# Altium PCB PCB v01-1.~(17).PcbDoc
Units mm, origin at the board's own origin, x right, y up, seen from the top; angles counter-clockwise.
Board outline 287 x 161 mm, 2 copper layers (Top Layer, Bottom Layer); 82 components, 36 nets, 164 pads, 8 vias.
Unrouted connection lines stored in the file: 30.
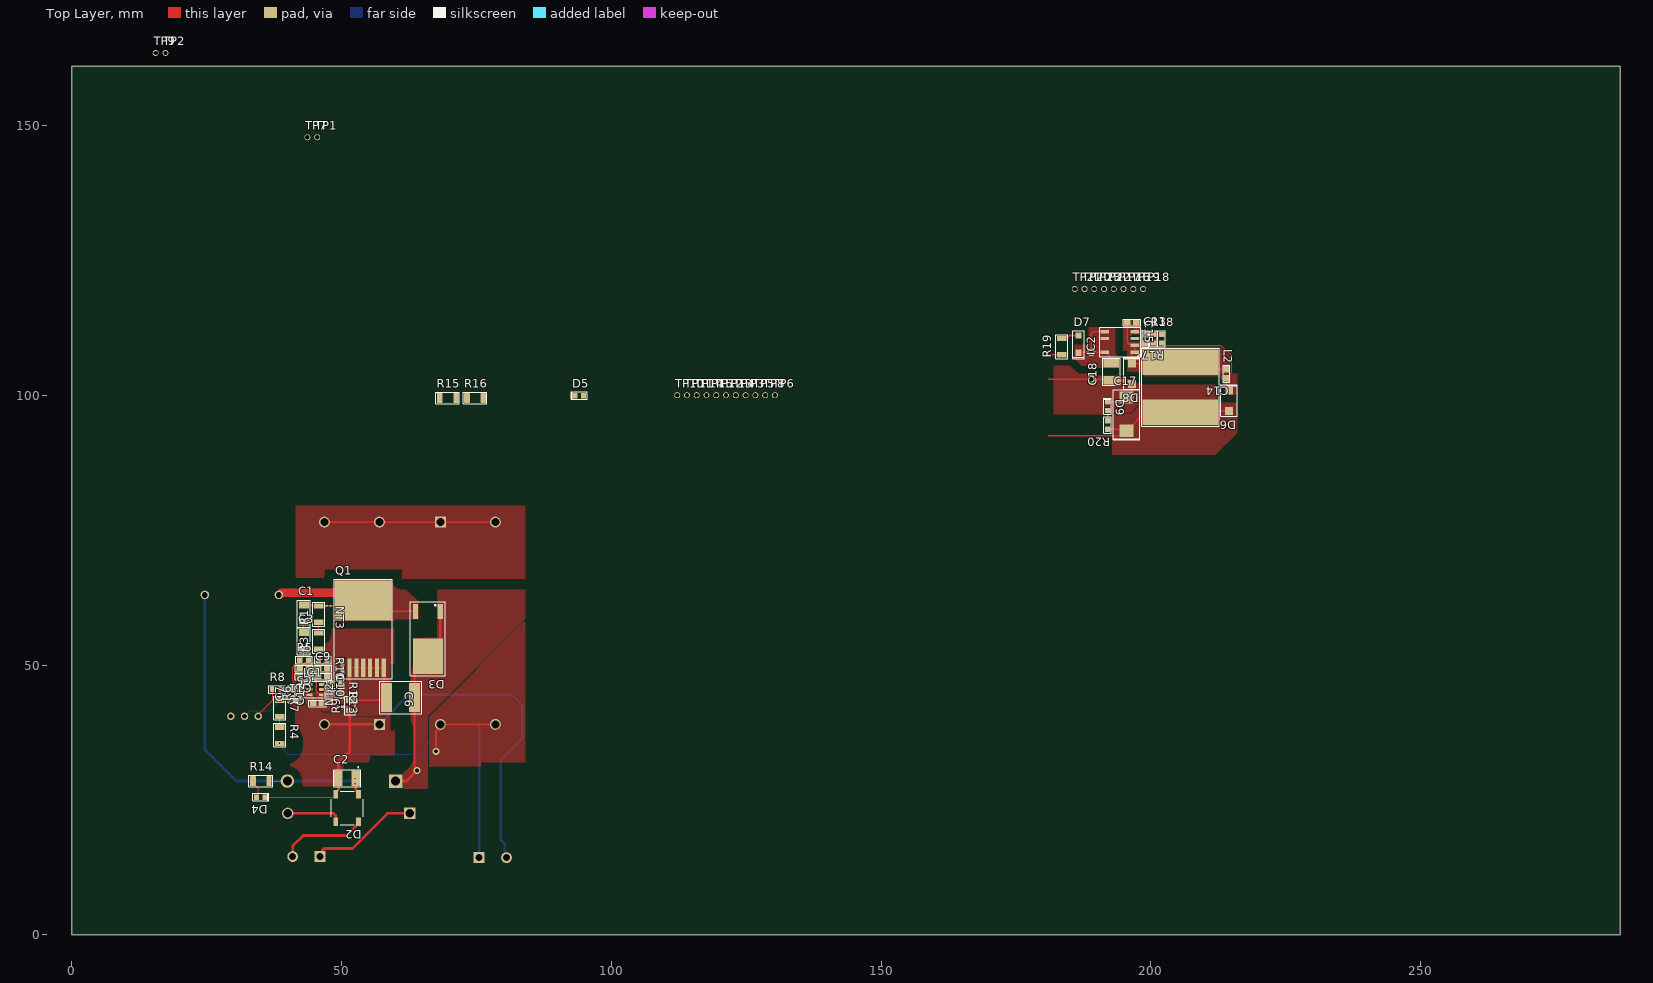
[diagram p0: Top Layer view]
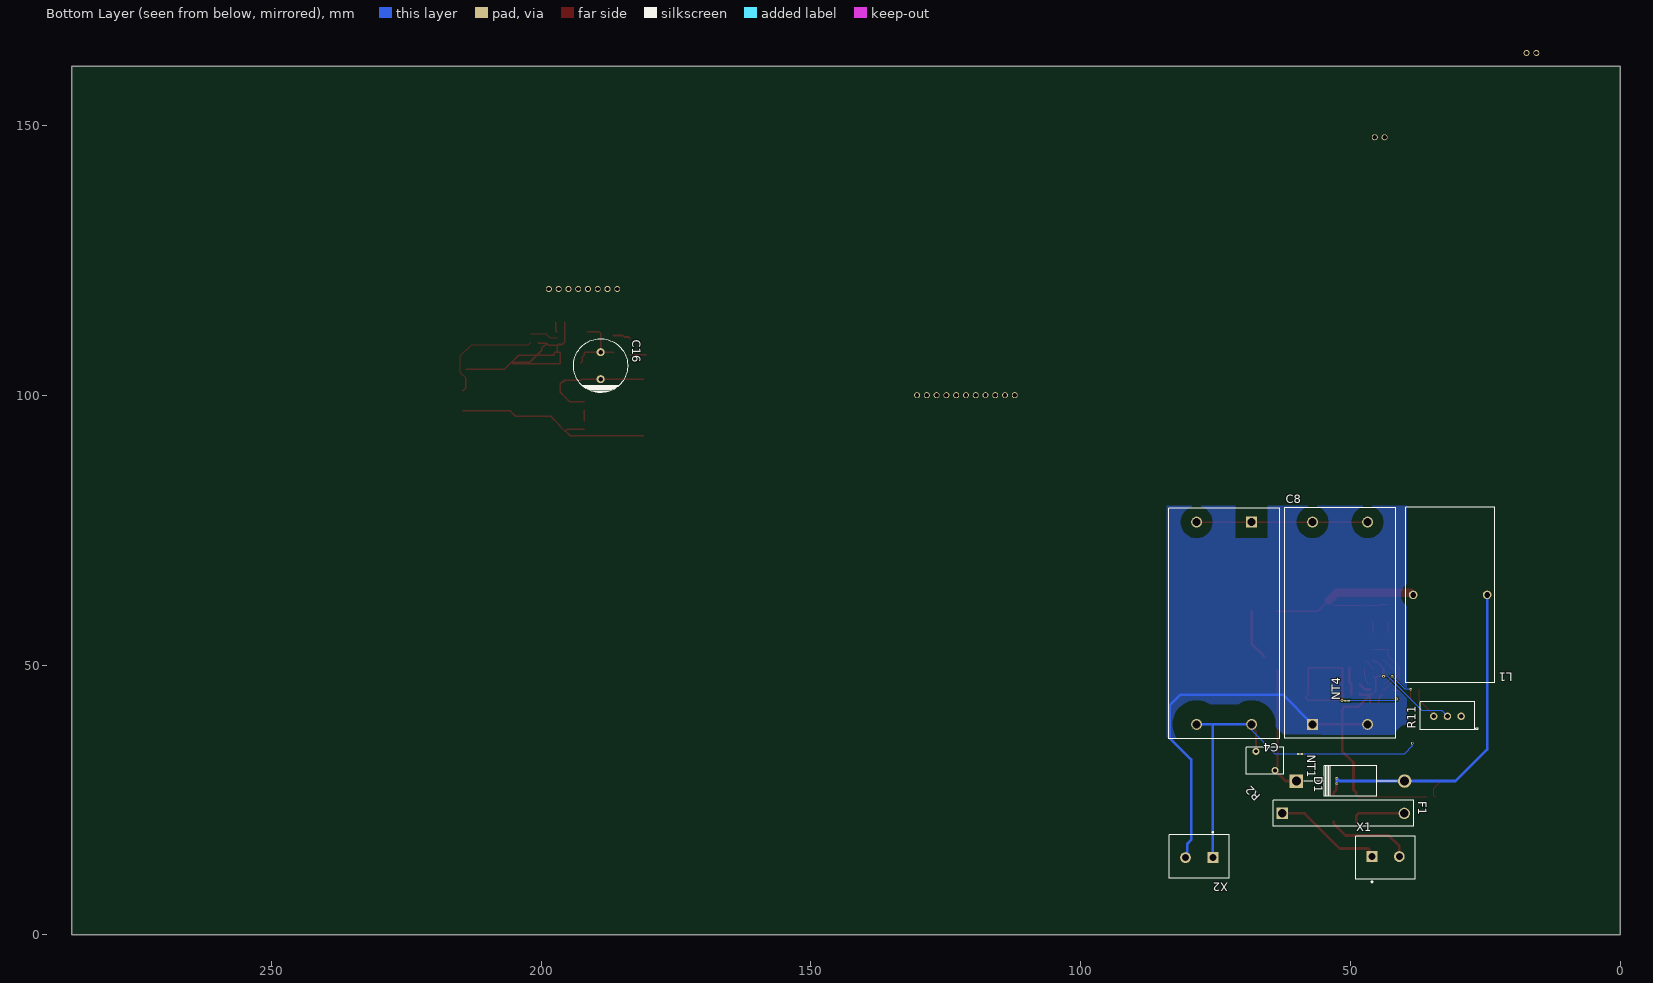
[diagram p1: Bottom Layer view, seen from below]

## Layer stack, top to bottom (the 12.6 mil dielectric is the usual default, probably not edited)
Top Solder: solder mask 0.0102, Solder Resist, Dk 3.5
Top Layer: signal copper 0.0356
Dielectric 1: dielectric 0.32, FR-4, Dk 4.8
Bottom Layer: signal copper 0.0356
Bottom Solder: solder mask 0.0102, Solder Resist, Dk 3.5

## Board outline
0,0 287,0 287,161 0,161

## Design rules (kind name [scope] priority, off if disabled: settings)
BoardOutlineClearance [All] p1: gap=1 ignorepadtopadclearanceinfootprint=FALSE
Clearance "1000V vs other" [InNetClass('1000V') vs Not InNetClass('1000V') AND Not InNetClass('500V')] p1: gap=3.5 ignorepadtopadclearanceinfootprint=TRUE
Clearance "500V vs other" [InNetClass('500V') vs Not InNetClass('500V')] p2: gap=2 ignorepadtopadclearanceinfootprint=TRUE
Clearance "375Vac vs other" [InNetClass('375Vac') vs Not InNetClass('375Vac')] p3: gap=1.5 ignorepadtopadclearanceinfootprint=FALSE
Clearance "375V vs other" [InNetClass('375V') vs Not InNetClass('375V')] p4: gap=1.5 ignorepadtopadclearanceinfootprint=FALSE
Clearance "AC vs ALL" [InNetClass('AC')] p5: gap=1.5 ignorepadtopadclearanceinfootprint=FALSE
Clearance Minimal [All] p6: gap=0.2 ignorepadtopadclearanceinfootprint=FALSE
Height [All] p1: minheight=0 maxheight=100 prefheight=12.7
HoleSize [All] p1: absolutevalues=TRUE maxlimit=10 minlimit=0.2 maxpercent=80.000 minpercent=20.000
PolygonConnect [All] p1: thpad.connectstyle=Relief thpad.reliefconductorwidth=0.254 thpad.reliefentries=4 thpad.polygonreliefangle="90 Angle" thpad.airgapwidth=0.2 smdpad.connectstyle=Relief smdpad.reliefconductorwidth=0.254 smdpad.reliefentries=4 smdpad.polygonreliefangle="90 Angle" smdpad.airgapwidth=0.2 via.connectstyle=Direct via.reliefconductorwidth=0.254 via.reliefentries=4 via.polygonreliefangle="90 Angle" via.airgapwidth=0.254
RoutingVias [All] p1: holewidth=0.2 width=0.5 viastyle="Through Hole" minholewidth=0.2 minwidth=0.5 maxholewidth=10 maxwidth=10
SolderMaskExpansion [All] p1: expansion=0.102 istentingtop=FALSE
Width [All] p1: maxlimit=20 minlimit=0.2 preferedwidth=0.3
28 further rules are at their usual default settings.

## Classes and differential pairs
net class 500V: NetC4_1 NetR4_1 NetR15_1
net class 1000V: NetC6_2 NetNT1_2 Udc
net class AC: L L_fuse N
net class 375V: HVIN NetD7_A ""
net class 375Vac: DRAIN FB NetC1_1 NetC1_2 NetC14_2 NetR1_1 SW VDD

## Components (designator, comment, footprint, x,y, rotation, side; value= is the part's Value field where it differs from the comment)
C1 "Generic Capacitor model" CAP_1206 43,59.55 r90 top
C2 "Generic Capacitor model" CAP_1210 51,29 r0 top
C3 "Generic Capacitor model" CAP_1206 43,54.4 r90 top
C4 "Generic Capacitor model" C4AQCBW5200A3FJ 68.3,76.5 r270 bottom
C5 "Generic Capacitor model" "CAP 0603" 43.025,49.4 r180 top
C6 "Generic Capacitor model" CAP_2220 58.34,44 r0 top
C7 "Generic Capacitor model" "CAP 0603" 40.7,44.65 r90 top
C8 "Generic Capacitor model" C4AQCBW5200A3FJ 57,39 r90 bottom
C9 "Generic Capacitor model" "CAP 0603" 46.525,49.4 r0 top
C10 "Generic Capacitor model" "CAP 0603" 46.525,47.9 r0 top
C11 "Generic Capacitor model" "CAP 0603" 43.025,47.9 r180 top
C12 "Generic Capacitor model" "CAP 0603" 45.525,42.9 r180 top
C13 "Generic Capacitor model" "CAP 0603" 199,110.5 r90 top
C14 "Generic Capacitor model" "CAP 0603" 214,104 r270 top
C15 "Generic Capacitor model" "CAP 0603" 196.5,113.5 r0 top
C16 "Cap_Polarized" "ELKO 10X20MM" 189,105.5 r270 bottom
C17 "Cap_Tantal" CAP_TANTAL_2917 195.5,96.5 r90 top
C18 "Generic Capacitor model" CAP_1210 192.7,104.4 r90 top
D1 "Diode" DO-201AD 60,28.5 r180 bottom
D2 "CD-MBL206SL" CD-MBL206SL 51,23.5 r270 top
D3 "Diode Schottky" TO252-2_DPAK_B 66,53.5 r180 top
D4 "Diode LED Red" DIODE_0603 35,25.5 r180 top
D5 "Diode LED Red" DIODE_0603 94.068,99.931 r0 top
D6 "Diode Schottky" SMAF 214.5,99 r270 top
D7 "Diode" SOD-123FL 186.6,109.5 r90 top
D8 "Diode Schottky" SMAF 196.5,104 r270 top
D9 "Diode LED Blue" DIODE_0603 192,98 r270 top
F1 "64600001003" 64600001003 62.6,22.5 r180 bottom
IC1 "UCC28056A" SOT-23-6 44.025,46.4 r0 top
IC2 "UCC28881" SOIC-7 197,108 r180 top
L1 "HCTI-680-3.4" HCTI-680-3.4 31.5,63 r0 bottom
L2 "SDR1307-681KL" SDR1307-681KL 205.5,101.5 r270 top
NT1 "NT" NETTIE_0.3MM 59.325,33.5 r180 bottom net-tie
NT2 "NT" NETTIE_0.5MM 49.75,42.25 r180 top net-tie
NT3 "NT" NETTIE_0.3MM 47.6,61 r0 top net-tie
NT4 "NT" NETTIE_0.3MM 50.6,43.4 r0 bottom net-tie
Q1 "Nmos_KS" "TO-263-7 D2PAK" 54,59.1 r0 top
R1 "Generic resistor model" RES_1206 45.75,59.4 r90 top
R2 "NTC 10R 1A" ICL101D05MIB 63.964,30.464 r45 bottom
R3 "Generic resistor model" RES_1206 45.75,54.4 r90 top
R4 "Generic resistor model" RES_1206 38.5,37.035 r270 top
R5 "Generic resistor model" RES_0603 43.025,50.9 r0 top
R6 "Generic resistor model" RES_0603 42.2,44.65 r90 top
R7 "Generic resistor model" RES_1206 38.5,42.04 r270 top
R8 "Generic resistor model" RES_0603 38,45.5 r0 top
R9 "Generic resistor model" Res_0805 51.5,42.5 r90 top
R10 "Generic resistor model" RES_0603 46.525,50.9 r0 top
R11 "67WR25KLF" RES-67WR10KLF 29.46,40.5 r0 bottom
R12 "Generic resistor model" RES_0603 49.025,46.4 r0 top
R13 "Generic resistor model" RES_0603 49.025,44.65 r0 top
R14 "Generic resistor model" RES_1206 35,28.5 r0 top
R15 "Generic resistor model" RES_1206 69.645,99.506 r0 top
R16 "Generic resistor model" RES_1206 74.703,99.506 r0 top
R17 "Generic resistor model" RES_0603 202,110.5 r270 top
R18 "Generic resistor model" RES_0603 200.5,110.5 r90 top
R19 "Generic resistor model" RES_1206 183.5,109 r90 top
R20 "Generic resistor model" RES_0603 192,94.5 r270 top
TP1 "Test Point" TEST_POINT_THT 45.456,147.84 r90 top
TP2 "Test Point" TEST_POINT_THT 17.325,163.482 r90 top
TP3 "Test Point" TEST_POINT_THT 124.888,100.029 r90 top
TP4 "Test Point" TEST_POINT_THT 123.077,100.029 r90 top
TP5 "Test Point" TEST_POINT_THT 126.699,100.029 r90 top
TP6 "Test Point" TEST_POINT_THT 130.322,100.029 r90 top
TP7 "Test Point" TEST_POINT_THT 43.644,147.84 r90 top
TP8 "Test Point" TEST_POINT_THT 128.51,100.029 r90 top
TP9 "Test Point" TEST_POINT_THT 15.514,163.482 r90 top
TP10 "Test Point" TEST_POINT_THT 112.21,100.029 r90 top
TP11 "Test Point" TEST_POINT_THT 114.021,100.029 r90 top
TP12 "Test Point" TEST_POINT_THT 119.454,100.029 r90 top
TP13 "Test Point" TEST_POINT_THT 121.266,100.029 r90 top
TP14 "Test Point" TEST_POINT_THT 115.832,100.029 r90 top
TP15 "Test Point" TEST_POINT_THT 117.643,100.029 r90 top
TP16 "Test Point" TEST_POINT_THT 194.962,119.716 r90 top
TP17 "Test Point" TEST_POINT_THT 193.15,119.716 r90 top
TP18 "Test Point" TEST_POINT_THT 198.584,119.716 r90 top
TP19 "Test Point" TEST_POINT_THT 196.773,119.716 r90 top
TP20 "Test Point" TEST_POINT_THT 187.717,119.716 r90 top
TP21 "Test Point" TEST_POINT_THT 185.906,119.716 r90 top
TP22 "Test Point" TEST_POINT_THT 191.339,119.716 r90 top
TP23 "Test Point" TEST_POINT_THT 189.528,119.716 r90 top
X1 "Screw Terminal 2pos" "Screw terminal 2pos 5.08mm" 43.485,14.3 r180 bottom
X2 "Screw Terminal 2pos" "Screw terminal 2pos 5.08mm" 78,14.5 r0 bottom

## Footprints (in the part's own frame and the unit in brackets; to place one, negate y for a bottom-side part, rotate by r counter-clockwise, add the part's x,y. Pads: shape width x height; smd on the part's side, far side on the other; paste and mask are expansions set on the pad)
64600001003 [mil] "Fuse holder 5x20mm"
  rect 83x83 / inner round 60 / far side rect 83x83 hole 63 paste-41.5 mask+0: 1(0,0)
  round 83 / inner round 60 / far side round 83 hole 63 paste-41.5 mask+0: 2(889.76,0)
  silkscreen extent -67,-94 961,94, body extent -62,-89 954,89, height 392
C4AQCBW5200A3FJ [mil] "Film Capacitor"
  round 79 hole 59 paste-39.5 mask+0: 1(0,-401.57) 2(1476.38,0) 2(1476.38,-401.58)
  rect 79x79 hole 59 paste-39.5 mask+0: 1(0,0)
  silkscreen extent -102,-606 1583,205, body extent -98,-602 1579,201, height 1583
"CAP 0603" [mm] "CAP 0603"
  rect 1.2x1 smd paste+0 mask+0: 1(-0.825,0) 2(0.825,0)
  silkscreen extent -1.6,-0.6 1.6,0.6, body extent -0.87,-0.48 0.87,0.48, height 0.87
CAP_1206 [mm]
  rect 1.3x1.8 smd: 1(-1.6,0) 2(1.6,0)
  silkscreen extent -2.5,-1.2 2.5,1.2, body extent -1.7,-0.9 1.7,0.9, height 1.81
CAP_1210 [mm] "Cap SMD 1210"
  rect 1.6x2.904 smd paste+0 mask+0: 1(-1.6,0) 2(1.6,0)
  silkscreen extent -2.5,-1.6 2.5,1.6, body extent -2.85,-1.95 2.85,1.95, height 0.25
CAP_2220 [mm] "CAP_2220"
  rect 2.01x5.4 smd: 1(0,0) 2(5.16,0)
  silkscreen extent -1.3,-3 6.5,3
CAP_TANTAL_2917 [mm] "CAP TANTAL 2917"
  rect 2.31x2.52 smd: +(-3.1,0) -(3.1,0)
  silkscreen extent -4.75,-2.5 4.5,2.5, body extent -3.65,-2.15 3.65,2.15, height 3.11
CD-MBL206SL [mil] "Rectifier bridge"
  rect 62.75x35.03 smd paste+0 mask+0: +(-100.37,82.5) -(-100.37,-82.5) AC1(100.37,82.5) AC2(100.37,-82.5)
  silkscreen extent -303,-114 122,114, body extent -116,-106 116,106, height 46
DIODE_0603 [mm] "RES 0603"
  rrect20% 0.94x1.02 smd: A(0.79,0) K(-0.79,0)
  silkscreen extent -1.5,-0.7 1.5,0.7, body extent -0.8,-0.4 0.8,0.4, height 0.46
DO-201AD [mm] "Diode THT Vishay"
  round 2.5 hole 1.651 paste-1.079 mask+0: A(20.066,0)
  rect 2.5x2.5 hole 1.651 paste-1.079 mask+0: K(0,0)
  silkscreen extent 1.4,-2.8 18.7,2.8, body extent -0.7,-2.67 20.76,2.67, height 5.34
"ELKO 10X20MM" [mm] "ELKO THT 10x20mm 5mm Pitch"
  round 1.5 hole 0.85: +(-2.5,0) -(2.5,0)
  silkscreen extent -5,-5 5,5, body extent -5,-5 5,5, height 20
HCTI-680-3.4 [mm] "Toroidal Inductor"
  round 1.6 hole 1.06: 1(-6.858,0) 2(6.858,0)
  silkscreen extent -8.25,-16.26 8.25,16.26, body extent -8.25,-16.21 8.26,16.21, height 34.27
ICL101D05MIB [mm] "NTC THT 5mm Disk"
  round 1.3 hole 0.7: 1(0,0) 2(5,0)
  silkscreen extent -1.67,-4.17 6.82,4.32
NETTIE_0.3MM [mm] "NetTie 0.3mm"
  rect 0.45x0.3 smd paste-5 mask+0.102: 1(-0.325,0) 2(0.325,0)
  Top Layer region: -0.125,0.15 0.125,0.15 0.125,-0.15 -0.125,-0.15
NETTIE_0.5MM [mm] "NetTie 0.5mm"
  rect 0.5x0.5 smd paste-5 mask+0.102: 1(-0.4,0) 2(0.4,0)
  Top Layer region: -0.175,-0.25 0.175,-0.25 0.175,0.25 -0.175,0.25
RES-67WR10KLF [mil] "Trimm Pot 10k"
  round 54 / inner round 60 / far side round 54 hole 34 paste-27 mask+0: 1(0,0) 2(100,0) 3(200,0)
  silkscreen extent -122,-105 300,100
RES_0603 [mm] "RES 0603"
  rrect20% 0.94x1.02 smd: 1(-0.79,0) 2(0.79,0)
  silkscreen extent -1.5,-0.7 1.5,0.7, body extent -0.8,-0.4 0.8,0.4, height 0.46
Res_0805 [mm]
  rrect25% 1x1.42 smd: 1(-0.925,-0.057) 2(0.945,-0.057)
  silkscreen extent -1.7,-1 1.7,0.9, body extent -1,-0.62 1,0.62, height 0.61
RES_1206 [mm]
  rrect14% 1.09x1.77 smd: 1(-1.465,0)
  rrect14% 0.94x1.77 smd: 2(1.54,0)
  silkscreen extent -2.2,-1.1 2.2,1.1, body extent -1.55,-0.78 1.55,0.77, height 0.56
"Screw terminal 2pos 5.08mm" [mm] "Screw terminal 2pos 5.08mm"
  rect 2x2 hole 1.3 paste-1000 mask+0: 1(-2.515,0.2)
  round 2 hole 1.3 paste-1000 mask+0: 2(2.565,0.2)
  silkscreen extent -5.56,-4.62 5.56,4, body extent -5.05,-3.93 5.11,4.07, height 10.02
SDR1307-681KL [mil] "Power inductor"
  rect 187x551 smd paste+0 mask+0: 1(-182,0) 2(182,0)
  silkscreen extent -283,-283 283,283
SMAF [mm] "DIODE SMAF"
  rect 1.46x1.53 smd: A(1.875,0) K(-1.875,0)
  silkscreen extent -3,-1.5 2.9,1.5, body extent -2.3,-1.3 2.3,1.3, height 1.11
SOD-123FL [mm]
  rect 1.18x1.17 smd: A(1.59,0) K(-1.59,0)
  silkscreen extent -2.7,-1.1 2.5,1.1, body extent -1.85,-0.95 1.85,0.95, height 1.35
SOIC-7 [mm] "SOIC-7"
  rect 1.55x0.6 smd: 1(0,0) 2(0,-1.27) 3(0,-2.54) 4(0,-3.81) 5(5.5,-3.81) 6(5.5,-2.54) 8(5.5,0)
  silkscreen extent -1.1,-4.6 6.5,0.8, body extent -0.2,-4.4 5.8,0.6, height 1.75
SOT-23-6 [mm]
  rect 1.072x0.532 smd: 1(0,0) 2(0,-0.95) 3(0,-1.9) 4(2.298,-1.9) 5(2.298,-0.95) 6(2.298,0)
  silkscreen extent -1.3,-2.5 3.2,0.6, body extent -0.3,-2.35 2.5,0.55, height 1.2
TEST_POINT_THT [mm] "Test point hole"
  round 1.1 hole 0.8: 1(0,0)
TO252-2_DPAK_B [mil] "Check internal diode connection pins!"
  rect 36.97x109.37 smd paste+0 mask+0: A(89.57,-253.97) K(-89.57,-253.97)
  rect 218x260 smd paste+0 mask+0: K(0,73)
  silkscreen extent -128,-325 128,217, body extent -132,-287 132,172, height 94
"TO-263-7 D2PAK" [mil] "SMD Mosfet"
  rect 409x294 smd paste+0 mask+0: D(0,113.5)
  rect 29.97x137.37 smd paste+0 mask+0: G(-150,-377.47) KS(-100,-377.47) S(-50,-377.47) S(0,-377.47) S(50,-377.47) S(100,-377.47) S(150,-377.47)
  silkscreen extent -213,-457 213,268, body extent -202,-424 202,241, height 180

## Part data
C1 C3: library part Cap, Capacitance=22p, Case Code (Imperial)=1206, Manufacturer=Walsin, Manufacturer Part Number=1206N220J102CT, Supplier Part Number 1=791-1206N220J102CT, Voltage Rating=1kV
C2 C18: library part Cap, Capacitance=100n, Case Code (Imperial)=1210, Manufacturer=Kemet, Manufacturer Part Number=C1210C104KBRACAUTO, Supplier Part Number 1=80-C1210C104KBRAUTO, Voltage Rating=630V
C4 C8: library part Cap, Capacitance=20u, Manufacturer=Kemet, Manufacturer Part Number=C4AQCBW5200A3FJ, Supplier Part Number 1=80-C4AQCBW5200A3FJ, Voltage Rating=650V
C5: library part Cap, Capacitance=10p, Case Code (Imperial)=0603, Manufacturer=Kemet, Manufacturer Part Number=C0603C100J1GAC, Supplier Part Number 1=80-C0603C100J1GAC, Voltage Rating=100V
C6: library part Cap, Capacitance=22n, Case Code (Imperial)=2220, Voltage Rating=2000V
C7: library part Cap, Capacitance=3n9, Case Code (Imperial)=0603, Manufacturer=Vishay, Manufacturer Part Number=VJ0603Y392KXACW1BC, Supplier Part Number 1=77-VJ0603Y392KXACBC, Voltage Rating=50V
C9 C14: library part Cap, Capacitance=180n, Case Code (Imperial)=0603, Manufacturer=Murata, Manufacturer Part Number=GCJ188R91H184KA01D, Supplier Part Number 1=81-GCJ188R91H184KA1D, Voltage Rating=50V
C10: library part Cap, Capacitance=82n, Case Code (Imperial)=0603, Manufacturer=Murata, Manufacturer Part Number=GCM188L81H823KA57D, Supplier Part Number 1=81-GCM188L81H823KA7D, Voltage Rating=50V
C11 C13: library part Cap, Capacitance=3n, Case Code (Imperial)=0603, Manufacturer=Murata, Manufacturer Part Number=GRM1885C1H302JA01D, Supplier Part Number 1=81-GRM1885C1H302JA1D, Voltage Rating=50V
C12 C15: library part Cap, Capacitance=3u3, Case Code (Imperial)=0603, Manufacturer=TDK, Manufacturer Part Number=C1608X5R1V335M080AC, Supplier Part Number 1=810-C1608X5R1V335M0C, Voltage Rating=35V
C16: "Generic polarized cap symbol", Capacitance=10u, Manufacturer=Panasonic, Manufacturer Part Number=EEU-EE2W100U, Supplier Part Number 1=667-EEU-EE2W100U, Voltage Rating=450V
C17: "Generic tantal cap symbol", Capacitance=100u, Manufacturer=Kemet, Manufacturer Part Number=T491X107M025AT, Supplier Part Number 1=80-T491X107M025, Voltage Rating=25V
D1: "General Diode symbol", Forward Current=3A, Manufacturer=Vishay, Manufacturer Part Number=BY255P-E3/73, Reverse Voltage=1300V, Supplier Part Number 1=625-BY255P-E3/73
D2: "Diode Bridge 600V 2A", Manufacturer=Bourns
D3: "General Schottky Diode symbol", Forward Current=2A, Manufacturer=Infineon, Manufacturer Part Number=IDM02G120C5XTMA1, Reverse Voltage=1200V, Supplier Part Number 1=726-IDM02G120C5XTMA1
D4 D5: "Generic red LED symbol"
D6 D8: "General Schottky Diode symbol", Forward Current=2A, Manufacturer=Comchip, Manufacturer Part Number=AES2JF-HF, Reverse Voltage=600V, Supplier Part Number 1=750-AES2JF-HF
D7: "General Diode symbol", Forward Current=1A, Manufacturer=MCC, Manufacturer Part Number=GS1Z-LTP, Reverse Voltage=2kV, Supplier Part Number 1=833-GS1Z-LTP
D9: "Generic blue LED symbol"
F1: "Fuse Holder 5X20MM 250V 6.3A", Manufacturer=Littlefuse, Supplier Part Number 1=576-64600001003
IC1: "PFC TM IC", Manufacturer="Texas Instruments"
IC2: "700-V Lowest Quiescent current off-line switcher", Manufacturer="Texas Instruments", Supplier Part Number 1=UCC28881D
L1: "Inductor THT 680uH 3.4A 150mR", Inductance=680u, Manufacturer="Bel Signal Transformer", Resistance=150mR, Saturation current=3.4Asat, Supplier Part Number 1=530-HCTI-680-3.4
L2: "Power Inductors - SMD 680uH 10% SMD 1307", Inductance=680u, Manufacturer=Bourns, Resistance=1R, Saturation current=1.2A, Supplier Part Number 1=652-SDR1307-681KL
NT1 NT2 NT3 NT4: library part NetTie, "Net Tie"
Q1: "Generic Nmos symbol with Kelvin Source", Manufacturer=GeneSiC, Manufacturer Part Number=G3R350MT12J, Supplier Part Number 1=905-G3R350MT12J, Voltage=1200V
R1 R3: library part Res, Case Code (Imperial)=1206, Manufacturer=ROHM, Manufacturer Part Number=KTR18EZPF4994, Resistance=4M99, Resistance Tolerance=1%, Supplier Part Number 1=755-KTR18EZPF4994
R2: library part ICL101D05MIB, "NTC 10R 1A 5mm THT", Manufacturer=Eaton, Resistance=10R, Supplier Part Number 1=504-ICL101D05MIB
R4 R7: library part Res, Case Code (Imperial)=1206, Manufacturer=ROHM, Manufacturer Part Number=KTR18EZPF5104, Resistance=5M1, Resistance Tolerance=1%, Supplier Part Number 1=755-KTR18EZPF5104
R5: library part Res, Case Code (Imperial)=0603, Manufacturer=Yageo, Manufacturer Part Number=AC0603JR-073KL, Resistance=3k, Supplier Part Number 1=603-AC0603JR-073KL
R6: library part Res, Case Code (Imperial)=0603, Manufacturer=Vishay, Manufacturer Part Number=CRCW060324K3FKEB, Resistance=24k3, Resistance Tolerance=1%, Supplier Part Number 1=71-CRCW060324K3FKEB
R8: library part Res, Case Code (Imperial)=0603, Manufacturer=Yageo, Manufacturer Part Number=RT0603DRE0725K5L, Resistance=25k5, Resistance Tolerance=1%, Supplier Part Number 1=603-RT0603DRE0725K5L
R9: library part Res, Case Code (Imperial)=0805, Manufacturer=Eaton, Manufacturer Part Number=MFLA0805R2000FA, Power Rating=250mW, Resistance=200mR, Supplier Part Number 1=504-MFLA0805R2000FA
R10: library part Res, Case Code (Imperial)=0603, Manufacturer=Panasonic, Manufacturer Part Number=ERJ-3EKF1653V, Resistance=165k, Resistance Tolerance=1%, Supplier Part Number 1=667-ERJ-3EKF1653V
R11: "Trimpot, 25 kohm, Through Hole, 20 Turns, Multi Turn, Cermet, Top Adjust,", Manufacturer="BI Technologies", Resistance=25k, Supplier Part Number 1=858-67WR25KLF
R12: library part Res, Case Code (Imperial)=0603, Power Rating=?mW, Resistance=10R, Resistance Tolerance=?%, Supplier Part Number 1=?
R13: library part Res, Case Code (Imperial)=0603, Power Rating=?mW, Resistance=82k, Resistance Tolerance=?%, Supplier Part Number 1=?
R14: library part Res, Case Code (Imperial)=1206, Manufacturer=KOA, Manufacturer Part Number=RN73H2BTTD3523F100, Power Rating=?mW, Resistance=352k, Resistance Tolerance=?%, Supplier Part Number 1=660-RN73H2BT3523F100
R15 R16: library part Res, Case Code (Imperial)=1206, Manufacturer=Yageo, Manufacturer Part Number=RT1206FRE07510KL, Power Rating=?mW, Resistance=510k, Resistance Tolerance=?%, Supplier Part Number 1=603-RT1206FRE07510KL
R17: library part Res, Case Code (Imperial)=0603, Manufacturer=Yageo, Manufacturer Part Number=RT0603BRD07135KL, Power Rating=?mW, Resistance=135k, Resistance Tolerance=1%, Supplier Part Number 1=603-RT0603BRD07135KL
R18: library part Res, Case Code (Imperial)=0603, Manufacturer=TE, Manufacturer Part Number=CRG0603F10K/10, Power Rating=?mW, Resistance=10k, Resistance Tolerance=1%, Supplier Part Number 1=279-CRG0603F10K/10
R19: library part Res, Case Code (Imperial)=1206, Manufacturer=Koa, Manufacturer Part Number=SG73P2BTTD100J, Power Rating=750mW, Resistance=10R, Supplier Part Number 1=660-SG73P2BTTD100J
R20: library part Res, Case Code (Imperial)=0603, Manufacturer=Kamaya, Manufacturer Part Number=RMC1/16K1502FTP, Resistance=15k, Supplier Part Number 1=791-RMC1/16K1502FTP
TP1 TP2 TP3 TP4 TP5 TP6 TP7 TP8 TP9 TP10 TP11 TP12 TP13 TP14 TP15 TP16 TP17 TP18 TP19 TP20 TP21 TP22 TP23: "Test point"
X1 X2: "Screw terminal 2 pos, pith 5.08mm", Color=Black, Current=15A, Current Rating=16A, Flammability Rating="UL94 V-0", Manufacturer=Weidmuller, Manufacturer Part Number=1760510000, Max Operating Temperature=120°C, Max Supply Voltage=300V, Min Operating Temperature=-50°C, Package Quantity=500, Supplier Part Number 1=4477091

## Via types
v1: diameter 0.5, hole 0.2, Top Layer to Bottom Layer, tented both sides, 8 vias

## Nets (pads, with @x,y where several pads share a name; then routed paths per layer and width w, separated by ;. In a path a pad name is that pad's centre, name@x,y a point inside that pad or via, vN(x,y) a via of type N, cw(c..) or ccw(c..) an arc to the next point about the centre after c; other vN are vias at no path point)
15V: C12.2 C17.+ D6.A IC1.3 L2.2 R20.2 TP19.1 | length 41.1
  Top Layer w0.3: IC1.3 44.295,44.5 44.411,44.384 44.411,44.114 44.7,43.825 C12.2 ; 181,92.5 194.6,92.5 C17.+ ; R20.2 195.19,93.71 C17.+ ; D6.A 205.748,97.125 L2.2 204.751,96.128 198.228,96.128 196.61,94.51 196.61,94.405 195.605,93.4 C17.+
COMP: C9.2 C10.2 IC1.6 TP13.1 | length 3.6
  Top Layer w0.2: IC1.6 46.57,46.4 46.736,46.566 46.736,46.813 47.14,47.217 47.14,47.69 C10.2 C9.2
DRAIN: D3.A L1.2 NT3.2 Q1.D TP8.1 | length 34.9
  Top Layer w0.2: NT3.2 53.017,61 Q1.D Q1.D@52.539,61.983
  Top Layer w0.3: Q1.D 56.032,59.951 D3.A
  Top Layer w1.5: L1.2 38.385,63 38.785,63.4 52.583,63.4 Q1.D
DRV: IC1.5 R12.1 | length 2.3
  Top Layer w0.5: IC1.5 47.285,45.45 47.975,46.14 48.015,46.14 48.235,46.36 R12.1
FB: C13.2 IC2.3 R17.1 R18.2 TP16.1 | length 5.4
  Top Layer w0.2: IC2.3 198.215,110.54 198.5,110.825 198.6,110.825 199,111.225 C13.2 200.465,111.325 R18.2 R17.1
GND: C5.1 C10.1 C11.1 C12.1 IC1.4 NT2.2 R10.1 R11.2 R13.1 TP4.1 TP5.1 TP6.1 | length 32
  Top Layer w0.3: C10.1@45.275,47.65 45.025,47.9 v1(43.85,47.9) C5.1 43.95,49.4 44.3,49.75 44.3,49.85 45.062,50.612 45.447,50.612 R10.1 ; C10.1 45.363,47.563 45.287,47.563 45.275,47.55 45.275,45.136 45.795,44.616 46.207,44.616 IC1.4 ; C12.1 IC1.4@46.35,44.473
  Top Layer w0.5: IC1.4@46.35,44.473 48.573,42.25 NT2.2 ; IC1.4@46.616,44.5 48.085,44.5 R13.1
  Bottom Layer w0.2: R11.2 32.986,41.486 36.686,41.486 43.1,47.9 v1(43.85,47.9)
HVIN: C16.+ C18.2 D7.K IC2.5 IC2.6 IC2.8 TP18.1 | length 13.8
  Top Layer w0.3: D7.K 186.69,108 C16.+ ; IC2.5 189.31,111.81 189,111.5 C16.+ ; C18.2 192.426,106.274 192.426,107.074 192.056,107.444 192.056,107.85 191.906,108 IC2.8 C16.+
L: F1.1 X1.1 | length 20.4
  Top Layer w0.5: X1.1 46.457,14.957 46.457,15.707 46.75,16 52,16 58.5,22.5 F1.1
L_fuse: D2.AC2 F1.2 TP1.1 | length 10.2
  Top Layer w0.5: F1.2 48.5,22.5 48.904,22.096 D2.AC2
N: D2.AC1 TP7.1 X1.2 | length 16.2
  Top Layer w0.5: X1.2 40.92,16.42 42.904,18.404 50.901,18.404 53.095,20.599 D2.AC1
NetC1_1: C1.1 C3.2 | length 2
  Top Layer w0.2: C3.2 C1.1
NetC1_2: C1.2 NT3.1 R1.2 | length 4.4
  Top Layer w0.2: C1.2 44.283,61.15 44.483,60.95 R1.2@45.74,60.95 ; R1.2 R1.2@45.74,60.95 ; NT3.1 45.79,61 R1.2@45.74,60.95
NetC3_1: C3.1 C7.2 R3.1 R5.1 R6.2 | length 13.3
  Top Layer w0.2: C7.2 40.975,45.2 41.467,45.2 ; R6.2 41.96,45.2 41.467,45.2 ; R3.1 45.615,52.8 C3.1 43,51.665 42.645,51.31 42.605,51.31 42.235,50.94 R5.1 42.235,50.86 41.865,50.49 41.825,50.49 41.535,50.2 41.476,50.2 40.9,49.624 40.9,47.11 41.467,46.543 41.467,45.2
NetC4_1: C4.1 C8.2 | length 31.7
  Top Layer w0.3: C8.2@46.8,76.5 57,76.5 68.3,76.5 C4.1@78.5,76.5
NetC6_2: C6.2 D1.K D3.K R2.1 | length 32.9
  Top Layer w0.3: D3.K@63.5,49.146 C6.2 63.5,31.14 63.964,30.676 R2.1
  Top Layer w0.5: D1.K 62,28.5 R2.1 ; D3.K@66,51.646 68.275,53.921 D3.K@68.275,59.951
NetC7_1: C7.1 NT4.1 R6.1 | length 10.7
  Top Layer w0.2: C7.1 40.825,43.7 v1(41.4,43.7) 42.04,43.7 R6.1
  Bottom Layer w0.2: v1(41.4,43.7) 41.7,43.4 NT4.1@50.2,43.4 ; NT4.1@50.15,43.35 NT4.1@50.2,43.4 ; NT4.1 NT4.1@50.2,43.4
NetC9_1: C9.1 R10.2 | length 2.3
  Top Layer w0.2: C9.1 45.8,49.4 46.2,49.8 46.2,49.9 46.79,50.49 46.945,50.49 47.315,50.86 R10.2
NetC14_2: C14.2 D6.K R17.2 | length 21.1
  Top Layer w0.2: R17.2 202.37,109.34 202.487,109.34 202.527,109.3 213,109.3 215,107.3 215,104.175 214.5,103.675 214.4,103.675 214,103.275 C14.2
  Top Layer w0.3: C14.2 214,101.375 D6.K
NetD4_A: D4.A R14.1 | length 3.5
  Top Layer w0.2: R14.1 33.535,28.16 34.5,27.195 34.5,25.79 D4.A
NetD5_A: D5.A R16.1
NetD7_A: D7.A R19.2 | length 3.3
  Top Layer w0.3: R19.2 183.773,110.813 184.634,110.813 184.911,111.09 D7.A
NetD9_A: D9.A R20.1 | length 1.9
  Top Layer w0.3: R20.1 D9.A
NetNT1_2: NT1.2 R4.2 | length 21.8
  Bottom Layer w0.2: v1(38.5,35.495) 38.5,35 ; 38.6,34.9 38.5,35 ; NT1.2 40,33.5 38.5,35
NetQ1_G: Q1.G R12.2 R13.2 TP12.1 | length 5
  Top Layer w0.5: R13.2 R12.2 49.815,46.44 50.19,46.815 Q1.G
NetR1_1: R1.1 R3.2 | length 2
  Top Layer w0.2: R3.2 R1.1
NetR4_1: R4.1 R7.2 | length 2
  Top Layer w0.2: R4.1 R7.2
NetR8_1: R8.1 R11.3 | length 6.1
  Top Layer w0.2: R11.3 34.54,40.817 34.874,41.151 34.874,41.16 35.423,41.709 37.21,43.496 R8.1
NetR15_1: R15.1 R16.2
PGND: C2.1 C8.1 C16.- C17.- C18.1 D2.- D4.K D5.K D8.A D9.K NT2.1 R9.1 TP9.1 TP15.1 TP22.1 TP23.1 X2.2 | length 125
  Top Layer w0.2: D4.K 48.56,25.5 48.904,25.845 D2.-
  Top Layer w0.3: 181,103 C16.- 192.5,103 C18.1 195.79,102.8 195.79,102.535 196.09,102.535 D8.A 196.5,100.6 C17.- 194.69,98.79 D9.K
  Top Layer w0.5: C8.1@46.8,39 51.324,39 ; D2.- 48.904,26.401 49.099,26.596 49.107,26.596 49.4,26.889 C2.1 49.4,31.9 51.5,34 51.5,39 ; NT2.1 51.324,42.25 R9.1@51.324,41.693 ; R9.1 51.5,41.517 51.5,39.176 ; C8.1@57,39 51.5,39 ; 51.324,39 51.5,39 ; 51.324,39 51.5,39.176 ; 51.5,39 51.5,39.176
  Bottom Layer w0.5: C8.1@57,39 62.5,44.5 81.5,44.5 83.5,42.5 83.5,36.5 79.5,32.5 79.5,17.588 80.235,16.853 80.235,15.343 80.278,15.3 80.278,14.587 X2.2
SOURCE: C6.1 NT4.2 Q1.KS Q1.S R9.2 TP14.1 | length 25.9
  Top Layer w0.3: R9.2@51.46,43.542 v1(51.557,43.445) 57.785,43.445 C6.1 57.81,44.53 57.81,49.512 56.54,49.512 55.27,49.512 54,49.512 52.73,49.512 Q1.KS R9.2@51.46,43.542
  Bottom Layer w0.2: NT4.2 50.937,43.412 51.525,43.412 v1(51.557,43.445)
SW: C13.1 C14.1 C15.1 D8.K IC2.1 IC2.2 L2.1 R18.1 TP20.1 TP21.1 | length 48.6
  Top Layer w0.3: C15.1 195.675,109.825 196.08,109.42 196.85,109.42 IC2.2 ; R18.1 200.465,109.675 C13.1 C13.1@199,109.62 ; C14.1 206.798,104.825 L2.1 ; IC2.1 196.65,108 196.5,107.85 D8.K 205.252,105.875 L2.1 ; IC2.1 197.406,108 197.556,107.85 197.556,107.444 L2.1@200.806,107.444 ; IC2.1 IC2.2 ; IC2.2 198.65,109.27 C13.1@199,109.62 ; C13.1@199,109.62 199,109.575 199.35,109.225 199.45,109.225 199.903,108.772 199.903,108.348 L2.1@200.806,107.444 ; L2.1@200.806,107.444 204.178,107.444 L2.1 ; L2.1@200.806,107.444 202.128,106.123 L2.1
Udc: C4.2 NT1.1 R2.2 R15.2 TP3.1 X2.1 | length 62
  Top Layer w0.3: R2.2 67.5,37.745 68.3,38.545 68.3,39 C4.2@78.5,39
  Bottom Layer w0.2: NT1.1 63.9,33.5 68.214,37.814 68.214,38.914 C4.2@68.3,39
  Bottom Layer w0.5: C4.2@68.3,39 75.5,39 ; X2.1 75.5,14.315 75.5,39 ; C4.2@78.5,39 75.5,39
VDD: C15.2 IC2.4 TP17.1 | length 1.9
  Top Layer w0.3: IC2.4 197.175,111.81 197.325,111.96 C15.2
VOSNS: C11.2 IC1.1 R7.1 R8.2 TP11.1 | length 9.1
  Top Layer w0.2: R7.1 38.79,43.795 v1(38.79,45.5) ; C11.2 v1(42.25,47.9) 42.3,47.9 42.7,47.5 42.7,47.4 43.534,46.566 43.859,46.566 IC1.1
  Bottom Layer w0.2: v1(38.79,45.5) 39.85,45.5 v1(42.25,47.9)
ZCD/CS: C5.2 IC1.2 R5.2 TP10.1 | length 8.5
  Top Layer w0.2: R5.2 43.448,50.533 43.233,50.533 42.7,50 42.7,49.8 42.3,49.4 42.1,49.4 41.7,49 41.7,48.817 41.583,48.7 41.476,48.7 41.3,48.524 41.3,47.276 41.476,47.1 42,47.1 43.266,45.834 43.472,45.834 43.589,45.717 43.589,45.616 43.755,45.45 IC1.2
"": C2.2 D1.A D2.+ L1.1 R14.2 R19.1 TP2.1 | length 69.7
  Top Layer w0.2: R14.2 D1.A
  Top Layer w0.3: 180.5,107.5 180.535,107.535 R19.1
  Top Layer w0.5: C2.2 52.6,26.889 52.893,26.596 52.901,26.596 53.095,26.401 D2.+
  Bottom Layer w0.5: L1.1 24.642,34.358 30.5,28.5 D1.A 52,28.5 v1(52.5,29) v1(52.5,28)
pads on no net: R11.1

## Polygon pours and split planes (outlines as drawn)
Udc on Top Layer "gg" (solid, pour order 16): 66,29 84,29 84,58.5 66,40.5
NetC6_2 on Top Layer "gg" (solid, pour order 15): 61,40.5 61,27 66,27 66,40.5
NetC6_2 on Top Layer "gg" (solid, pour order 14): 61,40.5 61,58 64.5,58 64.5,66 84,66 84,58.5 66,40.5
DRAIN on Top Layer "gg" (solid, pour order 13): 64.5,58 48.5,58 48.5,66 60,66 64.5,61.5
NetC4_1 on Top Layer "gg" (solid, pour order 12): 41.5,79.5 41.5,66 84,66 84,79.5
PGND on Top Layer "gg" (solid, pour order 11): 39.5,43.5 44.404,43.5 46.504,41.4 49.4,41.4 49.371,41.429 49.371,42 52.5,42 52.5,40.5 61,40.5 61,27.5 39.5,27.5
GND on Top Layer "gg" (solid, pour order 10): 49.1,43.9 49.4,43.9 49.4,41.4 46.504,41.4 45.704,42.2
SOURCE on Top Layer "gg" (solid, pour order 8): 46.9,58.2 61,58.2 61,40.5 52.5,40.5 52.5,41.971 49.4,41.971 49.4,47.2 48.1,47.2 48.1,51.5 48,51.6 46.9,51.6
GND on Top Layer "gg" (solid, pour order 7): 45.5,42.2 45.5,43.6 44.8,44.3 44.8,44.945 44.761,44.984 44.777,45 47.4,45 47.7,45.3 49.1,45.3 49.1,43.9 47.4,42.2
15V on Top Layer "gg" (solid, pour order 6): 43.2,45 44.8,45 44.8,44.3 45.5,43.6 45.5,42.2 43.9,42.2 43.2,42.9
PGND on Top Layer "gg" (solid, pour order 5): 192.9,96.5 196.3,96.5 198.3,98.5 198.3,103.5 197.5,104.3 194.9,104.3 194.145,105.055 194.145,105.1 190.3,105.1 189.9,105.5 182,105.5 182,96.5
NetC14_2 on Top Layer "gg" (solid, pour order 4): 216,99.5 213.3,99.5 212.7,100.1 212.7,103.5 213.2,104 216,104
15V on Top Layer "gg" (solid, pour order 3): 192.9,89 192.9,96.5 196.3,96.5 198.3,98.5 198.3,103.5 212.7,103.5 212.7,100.1 213.3,99.5 216,99.5 216,93 212,89
VDD on Top Layer "gg" (solid, pour order 1): 196.5,114.1 196.5,112.785 196.2,112.485 196.2,111.31 198.09,111.31 198.1,111.3 198.1,114.1
SW on Top Layer "gg" (solid, pour order 0): 196.5,114.1 194.9,114.1 194.9,104.3 197.5,104.3 198.3,103.5 212.7,103.5 213.2,104 214.6,104 214.6,107.3 212.9,109 201.4,109 201.3,109.1 201.3,110.5 198.5,110.5 197.9,109.9 196.6,109.9 196.5,110
HVIN on Top Layer "gg" (solid, pour order 2): 194.3,104.3 191.1,104.3 189.9,105.5 187.2,105.5 185.9,106.8 185.9,109.4 188.1,109.4 188.5,109.8 188.5,112.6 194.3,112.6
PGND on Bottom Layer "gg" (solid, pour order 17): 39.5,36.5 84,36.5 84,79.5 39.5,79.5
